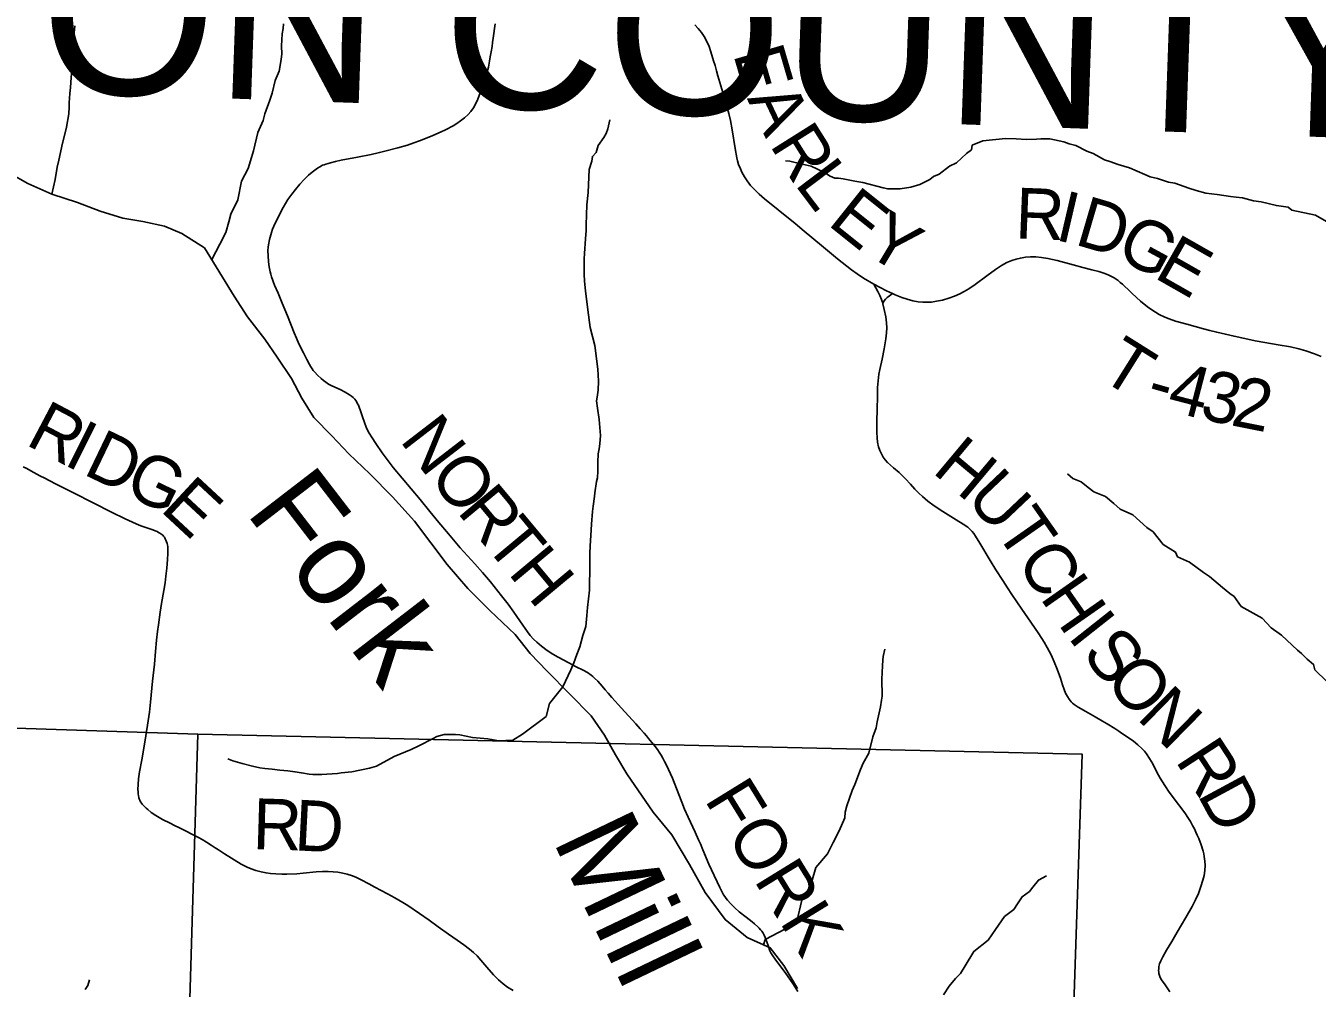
# Model space of a CAD drawing. Extents: x 6.3 to 40.3, y 9 to 31.
# Drawn here: x 11.141 to 12.585, y 27.918 to 28.995 of the extents above; entities that cross this region are included whole.
import ezdxf

# ---------------------------------------------------------------- set-up
doc = ezdxf.new("R2010")
doc.units = 0
for name, color, linetype in [('GM_X_County_Text', 7, 'Continuous'), ('GM_X_Minor_River', 7, 'Continuous'), ('GM_X_Minor_River_Text', 7, 'Continuous'), ('GM_X_Section', 7, 'Continuous'), ('GM_X_Township_Road', 7, 'Continuous'), ('GM_X_Township_Road_Text', 7, 'Continuous')]:
    doc.layers.add(name, color=color, linetype=linetype)

msp = doc.modelspace()

# ---------------------------------------------------------------- linework, layer by layer
at = {"layer": 'GM_X_Minor_River'}
for points in [[(11.349, 28.7332), (11.358, 28.7504), (11.3647, 28.7634), (11.368, 28.7756), (11.3702, 28.7839), (11.378, 28.8), (11.3823, 28.8209), (11.3898, 28.8351), (11.3934, 28.8476), (11.3956, 28.8549), (11.4007, 28.8754), (11.4063, 28.8888), (11.4085, 28.8964), (11.414, 28.9117), (11.4166, 28.9193), (11.4199, 28.9334), (11.4243, 28.9441), (11.4254, 28.9505), (11.4265, 28.9574), (11.4272, 28.9631), (11.4271, 28.9722), (11.4277, 28.9859), (11.4288, 28.9916), (11.4291, 28.9969)], [(11.1703, 28.8063), (11.1738, 28.8229), (11.1763, 28.8366), (11.1778, 28.8446), (11.1821, 28.8636), (11.1851, 28.875), (11.1865, 28.8815), (11.189, 28.8964), (11.1897, 28.904), (11.1896, 28.9085), (11.1903, 28.9192), (11.191, 28.9256), (11.1916, 28.937), (11.1927, 28.9454), (11.193, 28.9541), (11.1932, 28.9648), (11.1943, 28.972), (11.1946, 28.9789), (11.1949, 28.983), (11.1959, 28.9948)], [(11.7415, 28.2554), (11.7507, 28.2744), (11.7537, 28.2824), (11.7574, 28.2915), (11.7607, 28.3003), (11.764, 28.3129), (11.7673, 28.3228), (11.7683, 28.3353), (11.7693, 28.3441), (11.7714, 28.3635), (11.7713, 28.3714), (11.7716, 28.3844), (11.7717, 28.4049), (11.772, 28.4129), (11.7734, 28.4311), (11.7737, 28.4372), (11.7747, 28.4516), (11.7754, 28.4574), (11.7771, 28.4684), (11.7775, 28.4726), (11.7792, 28.4851), (11.7803, 28.4893), (11.7806, 28.4965), (11.7809, 28.5068), (11.7812, 28.5159), (11.7823, 28.5216), (11.783, 28.5273), (11.7836, 28.5365), (11.7823, 28.5543), (11.7803, 28.5672), (11.7794, 28.5752), (11.7798, 28.5794), (11.7812, 28.5873), (11.7815, 28.5972), (11.7806, 28.6109), (11.7773, 28.6371), (11.7721, 28.6575), (11.7696, 28.6769), (11.7671, 28.6985), (11.7659, 28.7091), (11.7654, 28.7171), (11.7654, 28.722), (11.7656, 28.7342), (11.7659, 28.7399), (11.7669, 28.7566), (11.7676, 28.7658), (11.7675, 28.7722), (11.7684, 28.7946), (11.7698, 28.8083), (11.7701, 28.8167), (11.771, 28.8342), (11.774, 28.8433), (11.7747, 28.8486), (11.7788, 28.8532), (11.781, 28.8609), (11.7874, 28.8697), (11.79, 28.8743), (11.7918, 28.8796), (11.794, 28.8895)], [(12.5957, 28.7757), (12.5831, 28.7828), (12.5568, 28.7886), (12.5526, 28.792), (12.5396, 28.7937), (12.5225, 28.7977), (12.5138, 28.7988), (12.5016, 28.8024), (12.4944, 28.8031), (12.4883, 28.8038), (12.4734, 28.8059), (12.4605, 28.8077), (12.4499, 28.8106), (12.4415, 28.8132), (12.4258, 28.8187), (12.419, 28.8198), (12.4064, 28.8238), (12.3984, 28.8257), (12.3923, 28.8283), (12.3752, 28.8357), (12.3626, 28.8397), (12.3534, 28.843), (12.3473, 28.8449), (12.3347, 28.852), (12.3275, 28.8545), (12.3153, 28.8609), (12.3077, 28.8627), (12.3019, 28.8649), (12.286, 28.8682), (12.2761, 28.8684), (12.2712, 28.868), (12.2601, 28.8675), (12.2484, 28.8685), (12.2366, 28.8688), (12.2112, 28.8662), (12.1995, 28.8611), (12.1984, 28.8562), (12.1931, 28.852), (12.1818, 28.8416), (12.1739, 28.8377), (12.1626, 28.8288), (12.1562, 28.8261), (12.152, 28.823), (12.1407, 28.8172), (12.1308, 28.8144), (12.1187, 28.8124), (12.105, 28.8123), (12.0997, 28.8134), (12.0769, 28.8196), (12.0681, 28.821), (12.0552, 28.8235), (12.0499, 28.8242), (12.0457, 28.8242), (12.0407, 28.8264), (12.0342, 28.8305), (12.0193, 28.8376), (12.0094, 28.8401), (11.9953, 28.8434), (11.9904, 28.8437)], [(11.4633, 28.5567), (11.4496, 28.5783), (11.4383, 28.6002), (11.422, 28.6243), (11.4084, 28.6443), (11.3891, 28.6693), (11.374, 28.6923), (11.341, 28.7463), (11.3157, 28.7625), (11.296, 28.7708), (11.2718, 28.7757), (11.2494, 28.7795), (11.2241, 28.7875), (11.1987, 28.7973), (11.1703, 28.8063), (11.1434, 28.8184), (11.1234, 28.8294)], [(12.0041, 27.9182), (11.9886, 27.9438), (11.9735, 27.9635), (11.9477, 27.9752), (11.9231, 27.9952), (11.9008, 28.0254), (11.8834, 28.0568), (11.8633, 28.09), (11.8425, 28.1153), (11.813, 28.1583), (11.8005, 28.1795), (11.788, 28.2014), (11.7733, 28.2229), (11.749, 28.2478), (11.7241, 28.2731), (11.7051, 28.2928), (11.6881, 28.3139), (11.6601, 28.3407), (11.6355, 28.3653), (11.6124, 28.3921), (11.5757, 28.4408), (11.5511, 28.468), (11.5257, 28.4937), (11.5023, 28.5159), (11.4833, 28.5363), (11.4633, 28.5567)], [(12.5961, 28.2613), (12.5827, 28.2744), (12.5811, 28.2805), (12.5738, 28.2865), (12.5677, 28.2929), (12.5631, 28.2963), (12.5454, 28.3132), (12.5336, 28.3214), (12.5236, 28.3323), (12.5003, 28.3454), (12.4922, 28.3563), (12.4876, 28.3597), (12.4792, 28.3664), (12.4646, 28.3788), (12.4581, 28.3833), (12.4424, 28.3949), (12.4291, 28.4009), (12.4268, 28.4061), (12.413, 28.4147), (12.4018, 28.4287), (12.3946, 28.4335), (12.3789, 28.4478), (12.3647, 28.4541), (12.3578, 28.4605), (12.3486, 28.4684), (12.3353, 28.4736), (12.3292, 28.4784), (12.3211, 28.4848), (12.312, 28.4885), (12.3058, 28.4938)], [(11.9658, 27.967), (11.968, 27.9727), (11.9975, 27.9886), (12.0031, 27.9929), (12.009, 28.0169), (12.018, 28.0287), (12.0198, 28.0367), (12.0245, 28.0535), (12.0377, 28.0688), (12.044, 28.0814), (12.0507, 28.0944), (12.057, 28.1089), (12.0573, 28.1154), (12.0591, 28.1222), (12.065, 28.1394), (12.068, 28.1463), (12.0743, 28.1631), (12.0776, 28.1699), (12.0836, 28.1814), (12.0883, 28.1997), (12.092, 28.2096), (12.0931, 28.2164), (12.0967, 28.2332), (12.0981, 28.2404), (12.0985, 28.245), (12.0983, 28.264), (12.0989, 28.2788), (12.0996, 28.2853), (12.0999, 28.2895), (12.1017, 28.2975)], [(11.7415, 28.2554), (11.7268, 28.2369), (11.7228, 28.2224), (11.6964, 28.2027), (11.6855, 28.1958), (11.6699, 28.1952), (11.6577, 28.1974), (11.6406, 28.1987), (11.6265, 28.2016), (11.6216, 28.2023), (11.6087, 28.2022), (11.6007, 28.1998), (11.5966, 28.1975), (11.5807, 28.1894), (11.572, 28.1855), (11.5531, 28.1777), (11.5331, 28.1668), (11.5255, 28.1644), (11.5058, 28.1604), (11.4937, 28.1592), (11.4895, 28.1587), (11.4778, 28.1579), (11.4721, 28.1574), (11.4622, 28.1573), (11.458, 28.1577), (11.4493, 28.1591), (11.442, 28.1605), (11.4341, 28.1616), (11.4253, 28.1622), (11.4166, 28.1633), (11.4082, 28.1643), (11.4029, 28.1647), (11.3945, 28.1669), (11.3831, 28.1698), (11.3724, 28.1727), (11.3671, 28.1749)], [(12.1673, 27.911), (12.1736, 27.9206), (12.1808, 27.9294), (12.1864, 27.9348), (12.1916, 27.9436), (12.2013, 27.9596), (12.2171, 27.9723), (12.2254, 27.9842), (12.2355, 27.9987), (12.246, 28.0065), (12.2501, 28.0126), (12.2554, 28.0206), (12.2633, 28.0264), (12.267, 28.0314), (12.2734, 28.0394), (12.2825, 28.0441)], [(11.2076, 27.9168), (11.2103, 27.9214), (11.2121, 27.9279)]]:
    msp.add_lwpolyline(points, dxfattribs=at)
at = {"layer": 'GM_X_Section'}
for points in [[(10.3378, 28.2352), (11.3334, 28.2025), (11.3031, 27.2038), (10.3113, 27.232)], [(11.3334, 28.2025), (12.3225, 28.18), (12.2889, 27.1733), (11.3031, 27.2038)]]:
    msp.add_lwpolyline(points, close=True, dxfattribs=at)
at = {"layer": 'GM_X_Township_Road'}
for points in [[(12.0045, 27.9147), (11.9989, 27.9237), (11.9936, 27.9313), (11.9902, 27.9358), (11.9797, 27.9496), (11.9755, 27.9558), (11.9742, 27.9579), (11.9731, 27.9601), (11.9714, 27.965), (11.9697, 27.9701), (11.9678, 27.9753), (11.9668, 27.9777), (11.9656, 27.9798), (11.9648, 27.981), (11.964, 27.9822), (11.9627, 27.9838), (11.9611, 27.9857), (11.9598, 27.987), (11.9561, 27.9904), (11.9532, 27.9928), (11.9466, 27.9977), (11.9389, 28.0038), (11.9338, 28.0083), (11.9293, 28.0127), (11.9256, 28.0169), (11.9241, 28.0188), (11.9226, 28.0208), (11.9213, 28.0229), (11.9201, 28.0251), (11.917, 28.0311), (11.9077, 28.0507), (11.905, 28.057), (11.8983, 28.073), (11.8954, 28.0798), (11.8934, 28.0844), (11.8895, 28.0928), (11.8817, 28.1097), (11.8777, 28.1188), (11.8747, 28.1265), (11.8687, 28.1419), (11.8641, 28.1533), (11.8597, 28.1631), (11.8576, 28.1678), (11.8554, 28.172), (11.8534, 28.1756), (11.8514, 28.1791), (11.8494, 28.1822), (11.8474, 28.1852), (11.8449, 28.1887), (11.8375, 28.1978), (11.8351, 28.2006), (11.8327, 28.2035), (11.8282, 28.2086), (11.8232, 28.2141), (11.8073, 28.2316), (11.7965, 28.2436), (11.7923, 28.2482), (11.7891, 28.252), (11.7855, 28.2562), (11.7807, 28.2618), (11.7771, 28.2653), (11.7752, 28.2671), (11.7733, 28.2685), (11.7692, 28.2713), (11.7643, 28.274), (11.7566, 28.2779), (11.7483, 28.2823), (11.7363, 28.2886), (11.7304, 28.2921), (11.7242, 28.2962), (11.7177, 28.301), (11.7124, 28.3054), (11.7089, 28.3088), (11.7051, 28.313), (11.7021, 28.3168), (11.6967, 28.3245), (11.6868, 28.3388), (11.6803, 28.3479), (11.6731, 28.3572), (11.6607, 28.3728), (11.6519, 28.3833), (11.6432, 28.393), (11.6269, 28.4109), (11.6212, 28.4175), (11.6138, 28.4266), (11.6029, 28.4394), (11.593, 28.4515), (11.582, 28.4648), (11.552, 28.5009), (11.5394, 28.5173), (11.5325, 28.5277), (11.5283, 28.5339), (11.5251, 28.5392), (11.5231, 28.5426), (11.5217, 28.5458), (11.5197, 28.551), (11.5174, 28.5575), (11.5152, 28.5642), (11.5137, 28.5683), (11.5129, 28.5704), (11.5121, 28.5721), (11.5108, 28.5745), (11.51, 28.5758), (11.5088, 28.5772), (11.507, 28.579), (11.5051, 28.5806), (11.5031, 28.582), (11.4981, 28.585), (11.4926, 28.5879), (11.4833, 28.5921), (11.4796, 28.5941), (11.4766, 28.5962), (11.474, 28.5981), (11.4713, 28.6003), (11.4674, 28.604), (11.4642, 28.6074), (11.4625, 28.6092), (11.4611, 28.6111), (11.4597, 28.6134), (11.4583, 28.6159), (11.4553, 28.6214), (11.4515, 28.6291), (11.4464, 28.6391), (11.4436, 28.6454), (11.4412, 28.6512), (11.4336, 28.6702), (11.4278, 28.6844), (11.4231, 28.6956), (11.4193, 28.7047), (11.4159, 28.7141), (11.415, 28.717), (11.4142, 28.7196), (11.4134, 28.7234), (11.4128, 28.7275), (11.4123, 28.7314), (11.4119, 28.737), (11.4118, 28.7435), (11.412, 28.7471), (11.4123, 28.7498), (11.4136, 28.7559), (11.4157, 28.7634), (11.4171, 28.7673), (11.4183, 28.7705), (11.4231, 28.7808), (11.4287, 28.7917), (11.4341, 28.8004), (11.4385, 28.8063), (11.4427, 28.8118), (11.4475, 28.8176), (11.4522, 28.823), (11.4572, 28.8276), (11.4614, 28.8311), (11.4672, 28.8354), (11.4698, 28.8371), (11.4729, 28.8387), (11.4747, 28.8394), (11.4765, 28.8401), (11.4818, 28.8415), (11.4872, 28.8428), (11.4938, 28.8443), (11.5119, 28.8477), (11.5272, 28.8509), (11.5349, 28.8527), (11.5426, 28.8546), (11.557, 28.8583), (11.5677, 28.8614), (11.575, 28.8638), (11.5813, 28.866), (11.5879, 28.8686), (11.5961, 28.872), (11.6055, 28.8761), (11.6102, 28.8785), (11.6189, 28.883), (11.6231, 28.8855), (11.6273, 28.8883), (11.6317, 28.8917), (11.6356, 28.8955), (11.6386, 28.8989), (11.6415, 28.9029), (11.6443, 28.9077), (11.6466, 28.9128), (11.6482, 28.9168), (11.6499, 28.9215), (11.6513, 28.9255), (11.6525, 28.9291), (11.6537, 28.9326), (11.6554, 28.9379), (11.6566, 28.942), (11.6583, 28.9486), (11.6597, 28.9553), (11.6605, 28.9602), (11.6614, 28.9656), (11.6625, 28.9717), (11.6631, 28.976), (11.6638, 28.9809), (11.666, 28.9969)], [(12.0893, 28.7057), (12.0778, 28.7126), (12.0708, 28.7172), (12.0645, 28.7219), (12.0489, 28.7341), (12.0329, 28.7471), (12.0199, 28.7579), (12.0115, 28.765), (12.0013, 28.7735), (11.9822, 28.7891), (11.9672, 28.8011), (11.961, 28.8064), (11.9562, 28.8111), (11.9516, 28.8162), (11.9478, 28.8212), (11.9447, 28.8258), (11.9416, 28.8312), (11.9401, 28.8346), (11.9381, 28.8398), (11.9369, 28.8439), (11.9361, 28.847), (11.9343, 28.8574), (11.931, 28.8783), (11.929, 28.8887), (11.9271, 28.8965), (11.9226, 28.9127), (11.9182, 28.9275), (11.915, 28.9389), (11.9135, 28.9442), (11.9118, 28.9502), (11.9102, 28.9556), (11.9071, 28.9657), (11.9051, 28.9715), (11.9026, 28.9772), (11.8997, 28.9827), (11.8966, 28.9874), (11.8931, 28.9918), (11.8893, 28.9959)], [(12.5897, 28.6249), (12.5822, 28.6279), (12.5723, 28.6314), (12.5645, 28.6336), (12.5554, 28.6356), (12.5414, 28.6381), (12.5267, 28.6405), (12.5158, 28.6425), (12.5007, 28.6456), (12.4922, 28.6475), (12.4826, 28.6497), (12.4729, 28.6521), (12.4651, 28.6541), (12.4579, 28.656), (12.4393, 28.6609), (12.4268, 28.6644), (12.4198, 28.6669), (12.4146, 28.669), (12.4085, 28.672), (12.4042, 28.6745), (12.3969, 28.6793), (12.3934, 28.6819), (12.3877, 28.6867), (12.383, 28.6907), (12.3777, 28.6959), (12.3736, 28.6997), (12.3702, 28.7033), (12.3675, 28.7057), (12.365, 28.7077), (12.3626, 28.7097), (12.3604, 28.7113), (12.3582, 28.7127), (12.3545, 28.7148), (12.3514, 28.7162), (12.3464, 28.7182), (12.3411, 28.7198), (12.3333, 28.7219), (12.3231, 28.7245), (12.3123, 28.7275), (12.2944, 28.7323), (12.2841, 28.7345), (12.2768, 28.7357), (12.2706, 28.7362), (12.2644, 28.7363), (12.2588, 28.7359), (12.2533, 28.735), (12.2485, 28.7339), (12.2437, 28.7324), (12.238, 28.7299), (12.232, 28.7266), (12.2253, 28.7222), (12.2158, 28.7152), (12.2028, 28.7055), (12.1957, 28.7006), (12.1904, 28.6974), (12.1854, 28.6948), (12.1797, 28.6923), (12.1733, 28.6901), (12.1661, 28.688), (12.1594, 28.6866), (12.1539, 28.6858), (12.1489, 28.6855), (12.144, 28.6856), (12.1391, 28.6862), (12.133, 28.6873), (12.1265, 28.689), (12.1206, 28.6909), (12.1132, 28.6939), (12.1103, 28.6953)], [(12.0994, 28.6846), (12.0981, 28.6887), (12.0962, 28.6932), (12.0939, 28.6976), (12.0893, 28.7057)], [(12.1103, 28.6953), (12.1037, 28.6983), (12.0893, 28.7057)], [(12.0994, 28.6846), (12.1011, 28.6872), (12.1024, 28.6889), (12.1032, 28.6898), (12.1041, 28.6907), (12.1054, 28.6918), (12.1069, 28.6929), (12.1103, 28.6953)], [(12.0929, 28.553), (12.0931, 28.5654), (12.0933, 28.581), (12.0936, 28.5903), (12.0942, 28.5977), (12.095, 28.605), (12.096, 28.6105), (12.0985, 28.622), (12.1009, 28.6336), (12.1027, 28.6446), (12.1036, 28.6514), (12.1038, 28.657), (12.1036, 28.6626), (12.1027, 28.6693), (12.1011, 28.6773), (12.0996, 28.6839), (12.0994, 28.6846)], [(12.4204, 27.9145), (12.415, 27.9221), (12.4111, 27.9277), (12.4097, 27.9305), (12.4087, 27.9328), (12.4082, 27.9347), (12.4079, 27.9364), (12.4078, 27.9383), (12.4079, 27.9401), (12.4082, 27.9425), (12.409, 27.9456), (12.4103, 27.9491), (12.4113, 27.9513), (12.4125, 27.9535), (12.4168, 27.9611), (12.4226, 27.9706), (12.4285, 27.9809), (12.4382, 27.9975), (12.4453, 28.0099), (12.449, 28.0171), (12.4523, 28.0245), (12.4552, 28.032), (12.4574, 28.0391), (12.4586, 28.0446), (12.4594, 28.0501), (12.4597, 28.0557), (12.4595, 28.0606), (12.4589, 28.0656), (12.4583, 28.0686), (12.4576, 28.0716), (12.4553, 28.0788), (12.4528, 28.0857), (12.4511, 28.0894), (12.4496, 28.0931), (12.4478, 28.0968), (12.4459, 28.1005), (12.4435, 28.1047), (12.4406, 28.1095), (12.4378, 28.1136), (12.4349, 28.1176), (12.4262, 28.1288), (12.4232, 28.1328), (12.4196, 28.1378), (12.4148, 28.145), (12.4122, 28.1492), (12.4096, 28.1534), (12.406, 28.1599), (12.4012, 28.1693), (12.3978, 28.1753), (12.3944, 28.1805), (12.3921, 28.1834), (12.3896, 28.1861), (12.3845, 28.1907), (12.3797, 28.1946), (12.3705, 28.2009), (12.3664, 28.2037), (12.3633, 28.2057), (12.3587, 28.2087), (12.3504, 28.2139), (12.345, 28.2171), (12.3367, 28.2218), (12.3265, 28.2277), (12.3179, 28.2326), (12.3134, 28.2357), (12.3117, 28.2371), (12.3102, 28.2386), (12.3078, 28.2415), (12.3058, 28.2446), (12.3037, 28.2484), (12.3021, 28.2524), (12.3003, 28.2577), (12.298, 28.2653), (12.2945, 28.2753), (12.2912, 28.2834), (12.2876, 28.2913), (12.2833, 28.2995), (12.2799, 28.3054), (12.2738, 28.3148), (12.2651, 28.3277), (12.2548, 28.3424), (12.2438, 28.3588), (12.239, 28.3661), (12.2362, 28.3702), (12.2335, 28.3743), (12.2258, 28.3863), (12.2193, 28.3969), (12.2079, 28.4162), (12.203, 28.4241), (12.2011, 28.4268), (12.1992, 28.4292), (12.1976, 28.431), (12.196, 28.4325), (12.1943, 28.4339), (12.1894, 28.4375), (12.1815, 28.4424), (12.1666, 28.4515), (12.1568, 28.458), (12.1498, 28.4632), (12.1436, 28.4683), (12.1395, 28.4721), (12.1351, 28.4765), (12.1302, 28.4821), (12.1247, 28.4881), (12.1222, 28.4908), (12.1195, 28.4933), (12.1177, 28.495), (12.1115, 28.5003), (12.1046, 28.5064), (12.1021, 28.5092), (12.1009, 28.5107), (12.0999, 28.5122), (12.0978, 28.516), (12.096, 28.5199), (12.0946, 28.524), (12.0936, 28.5289), (12.0931, 28.5338), (12.0928, 28.54), (12.0929, 28.5499), (12.0929, 28.553)], [(11.6862, 27.9158), (11.6798, 27.9196), (11.6748, 27.9232), (11.6696, 27.9276), (11.664, 27.9334), (11.6567, 27.9419), (11.6499, 27.9499), (11.6456, 27.9545), (11.6416, 27.9583), (11.6373, 27.962), (11.631, 27.9669), (11.6233, 27.9722), (11.6136, 27.9787), (11.602, 27.987), (11.5921, 27.9944), (11.5814, 28.0019), (11.5681, 28.011), (11.5628, 28.0142), (11.5536, 28.0194), (11.5455, 28.0239), (11.5313, 28.0315), (11.5248, 28.0351), (11.516, 28.0397), (11.5109, 28.0421), (11.5063, 28.0439), (11.5004, 28.0458), (11.4956, 28.047), (11.4901, 28.048), (11.4846, 28.0487), (11.479, 28.049), (11.4728, 28.0489), (11.4659, 28.0484), (11.4511, 28.047), (11.4443, 28.0464), (11.4331, 28.0459), (11.4275, 28.0459), (11.4207, 28.0462), (11.4146, 28.0467), (11.4097, 28.0473), (11.4043, 28.0484), (11.3983, 28.0501), (11.393, 28.0519), (11.3884, 28.0537), (11.3819, 28.0573), (11.3634, 28.0687), (11.3566, 28.0731), (11.3529, 28.0754), (11.3482, 28.0783), (11.343, 28.0817), (11.3382, 28.0846), (11.3342, 28.0868), (11.3283, 28.0898), (11.319, 28.0946), (11.3129, 28.0977), (11.3073, 28.1004), (11.3023, 28.1029), (11.294, 28.1072), (11.2865, 28.1116), (11.2813, 28.115), (11.2774, 28.1181), (11.2757, 28.1196), (11.274, 28.1212), (11.2722, 28.1231), (11.2712, 28.1243), (11.2705, 28.1253), (11.2694, 28.127), (11.2686, 28.1286), (11.2679, 28.1303), (11.2676, 28.1312), (11.2674, 28.132), (11.267, 28.1337), (11.2668, 28.1357), (11.2666, 28.138), (11.2665, 28.1406), (11.2666, 28.1462), (11.2671, 28.1524), (11.2682, 28.1604), (11.2707, 28.1738), (11.2743, 28.1934), (11.2773, 28.2124), (11.2793, 28.227), (11.2806, 28.2382), (11.2829, 28.2617), (11.2848, 28.2808), (11.286, 28.2951), (11.2873, 28.3075), (11.2884, 28.3175), (11.2894, 28.3247), (11.2913, 28.3389), (11.2929, 28.3487), (11.2954, 28.3633), (11.2968, 28.3716), (11.2978, 28.3793), (11.2986, 28.388), (11.2995, 28.3977), (11.3, 28.4047), (11.3, 28.4077), (11.2998, 28.4104), (11.2997, 28.4122), (11.2994, 28.4141), (11.299, 28.4159), (11.2985, 28.4176), (11.2977, 28.4195), (11.297, 28.4211), (11.2961, 28.4227), (11.2952, 28.4239), (11.2941, 28.4251), (11.293, 28.4259), (11.2911, 28.4272), (11.2895, 28.4281), (11.2878, 28.4291), (11.2856, 28.4301), (11.2832, 28.431), (11.2697, 28.4356), (11.2645, 28.4377), (11.2521, 28.4434), (11.237, 28.4508), (11.2165, 28.4612), (11.1944, 28.4725), (11.175, 28.4822), (11.1672, 28.4862), (11.1623, 28.4888), (11.1568, 28.4916), (11.1465, 28.4972), (11.1421, 28.4995), (11.1382, 28.5015)]]:
    msp.add_lwpolyline(points, dxfattribs=at)

# ---------------------------------------------------------------- texts
at = {"layer": 'GM_X_County_Text'}
msp.add_text('WASHINGTON COUNTY', height=0.189394, rotation=357.9773, dxfattribs=at).set_placement((9.7904, 28.9692))
at = {"layer": 'GM_X_Minor_River_Text'}
for s, height, rotation, p in [('Fork', 0.09472, 307.5921, (11.3858, 28.4509)), ('Mill', 0.09473, 295.5955, (11.7295, 28.0845))]:
    msp.add_text(s, height=height, rotation=rotation, dxfattribs=at).set_placement(p)
at = {"layer": 'GM_X_Township_Road_Text'}
for s, height, rotation, p in [('E', 0.0568, 286.2986, (11.9318, 28.9634)), ('A', 0.0568, 295.3216, (11.9472, 28.9135)), ('R', 0.0568, 302.184, (11.9721, 28.8618)), ('L', 0.0568, 307.0576, (12, 28.8179)), ('E', 0.0568, 321.3298, (12.0364, 28.773)), ('R', 0.0568, 357.7512, (12.2468, 28.7571)), ('I', 0.0568, 346.8802, (12.2906, 28.7556)), ('D', 0.0568, 343.6678, (12.3125, 28.7506)), ('Y', 0.0568, 329.0709, (12.0764, 28.7416)), ('G', 0.0568, 331.434, (12.3576, 28.7377)), ('E', 0.0568, 330.3747, (12.4012, 28.7139)), ('T', 0.0568, 327.891, (12.3398, 28.6016)), ('4', 0.0568, 345.3617, (12.4155, 28.5652)), ('3', 0.0568, 348.171, (12.4523, 28.5556)), ('-', 0.0568, 344.1323, (12.3918, 28.5719)), ('2', 0.0568, 348.7138, (12.4871, 28.5483)), ('R', 0.0568, 332.1991, (11.1394, 28.5271)), ('I', 0.0568, 333.467, (11.1819, 28.5047)), ('N', 0.0568, 307.597, (11.5583, 28.5312)), ('D', 0.0568, 334.3766, (11.2037, 28.4939)), ('H', 0.0568, 320.1301, (12.1534, 28.4959)), ('G', 0.0568, 334.3636, (11.2488, 28.4723)), ('O', 0.0568, 309.7265, (11.5903, 28.4897)), ('U', 0.0568, 313.4956, (12.1905, 28.465)), ('E', 0.0568, 317.1126, (11.2901, 28.4532)), ('R', 0.0568, 309.7547, (11.6223, 28.4513)), ('T', 0.0568, 309.7562, (11.6521, 28.4154)), ('T', 0.0568, 305.0191, (12.2235, 28.4305)), ('H', 0.0568, 309.7533, (11.6793, 28.3827)), ('C', 0.0568, 303.1423, (12.2476, 28.3961)), ('H', 0.0568, 305.0038, (12.2743, 28.3553)), ('I', 0.0568, 308.3432, (12.3051, 28.3115)), ('S', 0.0568, 309.9516, (12.3207, 28.2918)), ('O', 0.0568, 311.1665, (12.3461, 28.2614)), ('N', 0.0568, 315.5722, (12.3823, 28.2203)), ('R', 0.0568, 303.2354, (12.4256, 28.1732)), ('FORK', 0.05682, 301.6371, (11.8992, 28.1294)), ('D', 0.0568, 298.3785, (12.4506, 28.1353)), ('R', 0.0568, 358.3137, (11.3942, 28.0741)), ('D', 0.0568, 357.0445, (11.4405, 28.0727))]:
    msp.add_text(s, height=height, rotation=rotation, dxfattribs=at).set_placement(p)

doc.saveas('drawing.dxf')
